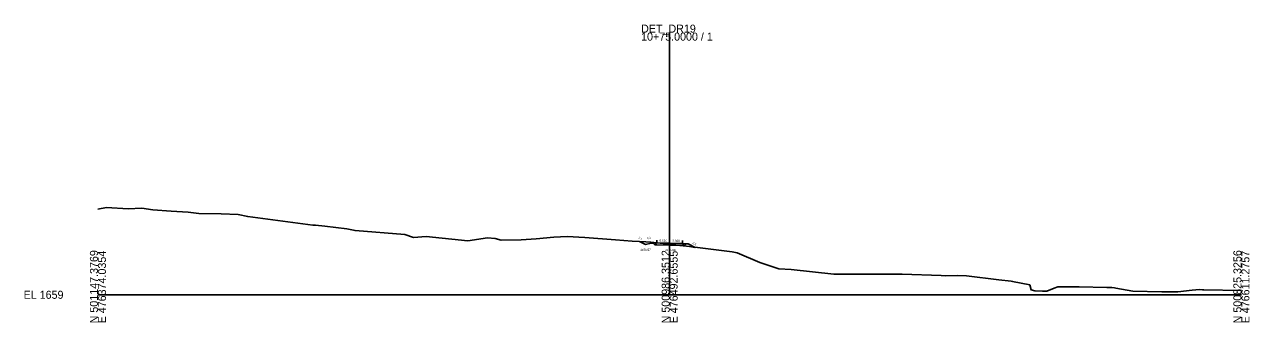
# Model space of a CAD drawing. Extents: x -26 to 403, y -10 to 3059.
# Drawn here: x -25.7 to 402.8, y 990.3 to 1094.5 of the extents above; entities that cross this region are included whole.
import ezdxf

# ---------------------------------------------------------------- set-up
doc = ezdxf.new("R2010")
doc.units = 0
for name, color, linetype in [('Exist Cross Section Cell', 7, 'Continuous'), ('Exist XS Center Line Elevation Label', 7, 'Continuous'), ('Exist XS Ground Line', 7, 'Continuous'), ('Prop XS Ditch Slope Text', 7, 'Continuous'), ('Prop XS Ditch Standard Text', 7, 'Continuous'), ('Prop XS Dump Level', 7, 'Continuous'), ('Prop XS Earthwork Shape', 7, 'Continuous'), ('Prop XS EOT Tick Mark', 7, 'Continuous'), ('Prop XS Finish Grade', 7, 'Continuous'), ('Prop XS Finish Grade Earthwork', 7, 'Continuous'), ('Prop XS Finish Grade Pavement', 7, 'Continuous'), ('Prop XS Hydro Typical Ditch Data', 7, 'Continuous'), ('Prop XS Pvmt Edge Slope', 7, 'Continuous'), ('Prop XS SE Text', 7, 'Continuous'), ('Prop XS Shoulder Borrow Shape', 7, 'Continuous'), ('Prop XS Side Slope Text', 7, 'Continuous'), ('Prop XS Subgrade Earthwork', 7, 'Continuous')]:
    doc.layers.add(name, color=color, linetype=linetype)

msp = doc.modelspace()

# ---------------------------------------------------------------- linework, layer by layer
at = {"layer": 'Exist Cross Section Cell'}
for p, q in [((200, 1000), (200, 1091.68)), ((0, 1000), (200, 1000)), ((200, 1000), (400, 1000))]:
    msp.add_line(p, q, dxfattribs=at)
at = {"layer": 'Exist XS Ground Line'}
msp.add_lwpolyline([(0, 1029.94), (3, 1030.56), (10.62, 1030.1), (15.39, 1030.3), (19.19, 1029.76), (25.57, 1029.21), (31.53, 1028.86), (35.31, 1028.46), (43.11, 1028.29), (49.09, 1028.06), (52.4, 1027.33), (75.15, 1024.4), (76.15, 1024.29), (79.36, 1023.97), (87.03, 1023.08), (89.95, 1022.46), (107.31, 1021.06), (110.35, 1020.05), (114.77, 1020.37), (129.4, 1018.87), (136.27, 1019.97), (138.91, 1019.7), (141.07, 1019.11), (148, 1019.23), (153.35, 1019.61), (159.49, 1020.1), (164.2, 1020.39), (170.29, 1019.98), (181.07, 1019.18), (186.9, 1018.76), (191.66, 1018.47), (193.42, 1018.38), (200, 1017.68), (203.66, 1017.29), (206.96, 1016.83), (221.89, 1014.98), (223.61, 1014.68), (231.57, 1011.32), (238.16, 1009.09), (242.5, 1008.89), (257.48, 1007.22), (264.96, 1007.17), (281.3, 1007.15), (295.02, 1006.69), (296.47, 1006.64), (300.86, 1006.7), (303.84, 1006.59), (315.19, 1005.22), (319.43, 1004.77), (319.94, 1004.7), (325.97, 1003.47), (326.45, 1001.7), (327.73, 1001.36), (330.45, 1001.24), (331.89, 1001.22), (334.52, 1002.33), (335.79, 1002.76), (343.21, 1002.77), (352.92, 1002.49), (354.16, 1002.49), (354.72, 1002.5), (355.56, 1002.41), (356.07, 1002.34), (362.05, 1001.24), (372.15, 1001.07), (377.77, 1001.03), (382.83, 1001.62), (385.33, 1001.79), (386.45, 1001.77), (386.83, 1001.76), (400, 1001.47)], dxfattribs=at)
at = {"layer": 'Prop XS Dump Level'}
for p, q in [((195.5, 1018.15), (200, 1018.06)), ((200, 1018.06), (204.5, 1017.97))]:
    msp.add_line(p, q, dxfattribs=at)
at = {"layer": 'Prop XS Earthwork Shape'}
for points in [[(200, 1017.4), (195.5, 1017.49), (194.85, 1017.5), (194.24, 1018.1), (193.5, 1018.07), (191.5, 1017.57), (189.43, 1018.61), (191.66, 1018.47), (193.42, 1018.38), (200, 1017.68), (203.32, 1017.33)], [(205.76, 1017.87), (206.5, 1017.81), (208.97, 1016.58), (206.96, 1016.83), (203.66, 1017.29), (203.32, 1017.33), (204.5, 1017.31), (205.18, 1017.29)]]:
    msp.add_lwpolyline(points, close=True, dxfattribs=at)
at = {"layer": 'Prop XS EOT Tick Mark'}
for p, q in [((195.5, 1018.15), (195.5, 1019.15)), ((204.5, 1017.97), (204.5, 1018.97))]:
    msp.add_line(p, q, dxfattribs=at)
at = {"layer": 'Prop XS Finish Grade'}
for p, q in [((195.5, 1018.15), (194.24, 1018.1)), ((204.5, 1017.97), (205.76, 1017.87))]:
    msp.add_line(p, q, dxfattribs=at)
at = {"layer": 'Prop XS Finish Grade Earthwork'}
for p, q in [((191.5, 1017.57), (189.43, 1018.61)), ((193.5, 1018.07), (191.5, 1017.57)), ((194.24, 1018.1), (193.5, 1018.07)), ((205.76, 1017.87), (206.5, 1017.81)), ((206.5, 1017.81), (208.97, 1016.58))]:
    msp.add_line(p, q, dxfattribs=at)
at = {"layer": 'Prop XS Finish Grade Pavement'}
for p, q in [((195.5, 1018.15), (200, 1018.06)), ((200, 1018.06), (204.5, 1017.97))]:
    msp.add_line(p, q, dxfattribs=at)
at = {"layer": 'Prop XS Hydro Typical Ditch Data'}
msp.add_line((191.5, 1017.57), (189.43, 1018.61), dxfattribs=at)
at = {"layer": 'Prop XS Pvmt Edge Slope'}
for p, q in [((195.5, 1018.15), (194.85, 1017.5)), ((204.5, 1017.97), (205.18, 1017.29))]:
    msp.add_line(p, q, dxfattribs=at)
at = {"layer": 'Prop XS Shoulder Borrow Shape'}
for points in [[(195.5, 1018.15), (194.85, 1017.5), (194.24, 1018.1)], [(205.18, 1017.29), (205.76, 1017.87), (204.5, 1017.97)]]:
    msp.add_lwpolyline(points, close=True, dxfattribs=at)
at = {"layer": 'Prop XS Subgrade Earthwork'}
for p, q in [((194.85, 1017.5), (194.24, 1018.1)), ((195.5, 1017.49), (194.85, 1017.5)), ((200, 1017.4), (195.5, 1017.49)), ((204.5, 1017.31), (200, 1017.4)), ((204.5, 1017.31), (205.18, 1017.29)), ((205.18, 1017.29), (205.76, 1017.87))]:
    msp.add_line(p, q, dxfattribs=at)

# ---------------------------------------------------------------- texts
at = {"layer": 'Exist Cross Section Cell'}
for s, p in [('DET_DR19', (190, 1091.68)), ('10+75.0000 / 1', (190, 1088.88)), ('EL 1659', (-26, 998.6))]:
    msp.add_text(s, height=2.8, dxfattribs=at).set_placement(p)
for s, p in [('N 501147.3769', (0, 990)), ('E 476374.0354', (2.8, 990)), ('N 500986.3512', (200, 990)), ('E 476492.6555', (202.8, 990)), ('N 500825.3256', (400, 990)), ('E 476611.2757', (402.8, 990))]:
    msp.add_text(s, height=2.8, rotation=90, dxfattribs=at).set_placement(p)
at = {"layer": 'Exist XS Center Line Elevation Label'}
msp.add_text('1676.68', height=0.75, dxfattribs=at).set_placement((198.3, 1015.31))
at = {"layer": 'Prop XS Ditch Slope Text'}
msp.add_text('4:1', height=0.75, rotation=14.0362, dxfattribs=at).set_placement((192.14, 1019.28))
at = {"layer": 'Prop XS Ditch Standard Text'}
msp.add_text('1676.57', height=0.75, dxfattribs=at).set_placement((189.68, 1015.32))
at = {"layer": 'Prop XS Dump Level'}
for p in [(193.5, 1018.03), (206.5, 1017.77)]:
    msp.add_text('Case1', height=0.04, dxfattribs=at).set_placement(p)
at = {"layer": 'Prop XS SE Text'}
for p in [(196.44, 1018.63), (200.94, 1018.54)]:
    msp.add_text('0.020', height=0.75, rotation=358.8542, dxfattribs=at).set_placement(p)
at = {"layer": 'Prop XS Side Slope Text'}
for p in [(188.96, 1019.7), (207.88, 1017.84)]:
    msp.add_text('2:1', height=0.75, rotation=333.4349, dxfattribs=at).set_placement(p)

doc.saveas('drawing.dxf')
